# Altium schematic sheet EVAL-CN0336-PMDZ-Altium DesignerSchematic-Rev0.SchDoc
size A
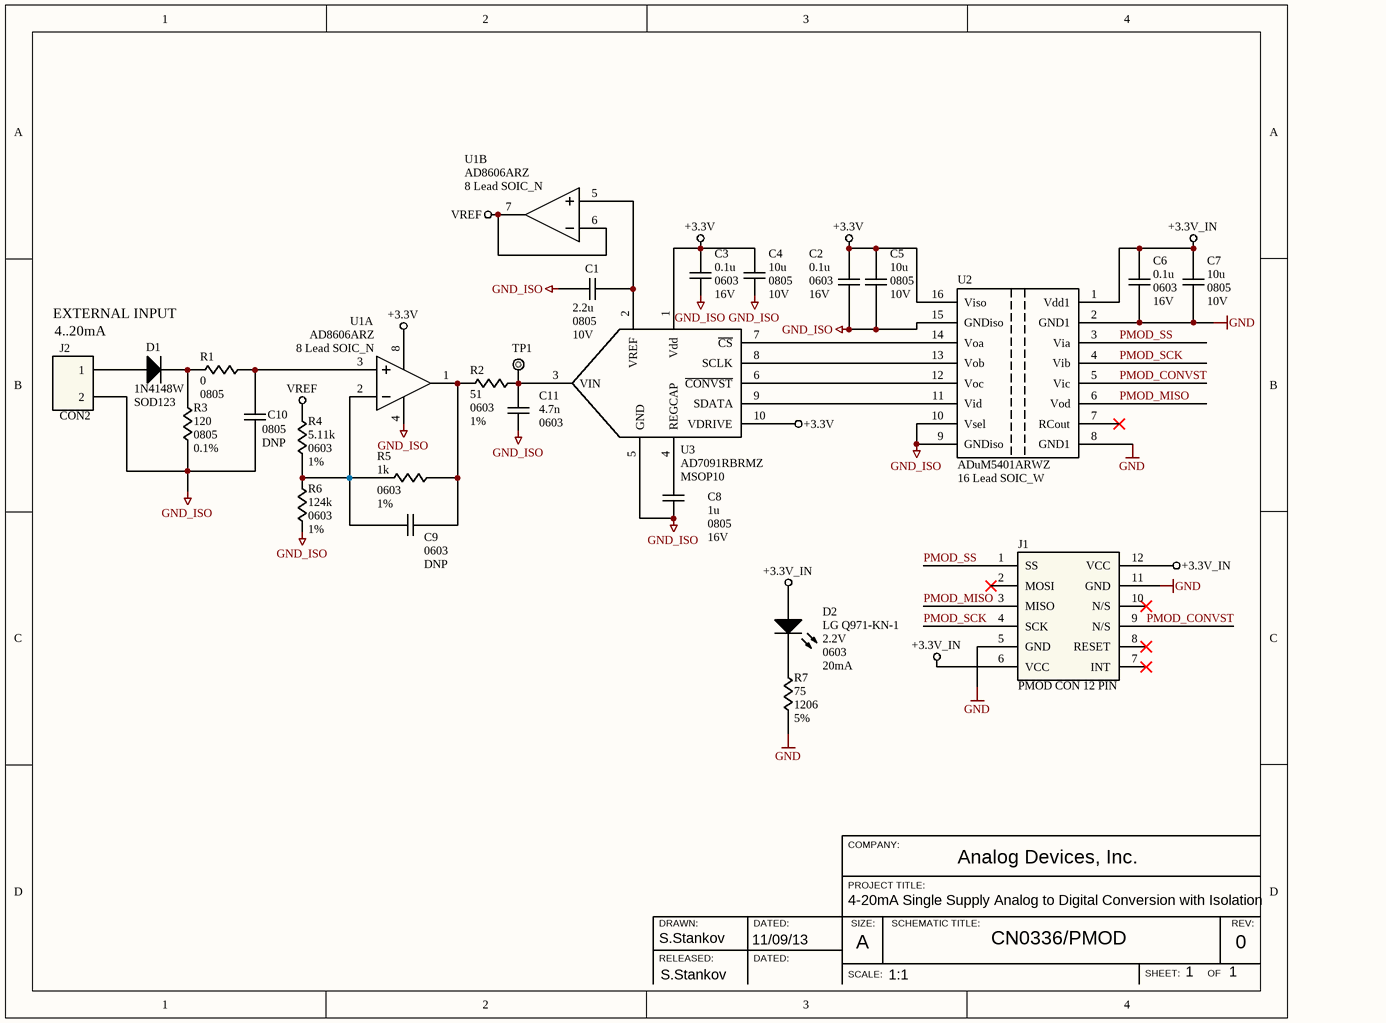
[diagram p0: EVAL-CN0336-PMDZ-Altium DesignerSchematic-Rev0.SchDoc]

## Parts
C1  value 2.2u  Footprint: 0805  Voltage: 10V  [0805 AD]
C2  value 0.1u  Footprint: 0603  Voltage: 16V  [0603 AD]
C3  value 0.1u  Footprint: 0603  Voltage: 16V  [0603 AD]
C4  value 10u  Footprint: 0805  Voltage: 10V  [0805 AD]
C5  value 10u  Footprint: 0805  Voltage: 10V  [0805 AD]  (hidden comment: Cap)
C6  value 0.1u  Footprint: 0603  Voltage: 16V  [0603 AD]
C7  value 10u  Footprint: 0805  Voltage: 10V  [0805 AD]  (hidden comment: Cap)
C8  value 1u  Footprint: 0805  Voltage: 16V  [0805 AD]
C9  Footprint: 0603  Part Number: DNP  [0603 AD]
C10  Footprint: 0805  Part Number: DNP  [0805 AD]
C11  value 4.7n  Footprint: 0603  [0603 AD]
D1  value 1N4148W  [SOD123]
D2  value LG Q971-KN-1  Drop Voltage: 2.2V  Footprint: 0603  Current: 20mA  [0603 Diode]  (hidden comment: LED3)
J1  PMOD CON 12 Pin  [PMOD 12 Pin]
J2  CON 2  [Phoenix Klema pitch 2_54]  (value not drawn)
R1  value 0  Footrprint: 0805  [0805 AD]  (hidden comment: RESISTOR)
R2  value 51  Footrprint: 0603  Tolerance: 1%  [0603 AD]  (hidden comment: RESISTOR)
R3  value 120  Footrprint: 0805  Tolerance: 0.1%  [0805 AD]  (hidden comment: RESISTOR)
R4  value 5.11k  Footrprint: 0603  Tolerance: 1%  [0603 AD]  (hidden comment: RESISTOR)
R5  value 1k  Footrprint: 0603  Tolerance: 1%  [0603 AD]  (hidden comment: RESISTOR)
R6  value 124k  Footrprint: 0603  Tolerance: 1%  [0603 AD]  (hidden comment: RESISTOR)
R7  value 75  Footrprint: 1206  Tolerance: 5%  [1206 AD]  (hidden comment: RESISTOR)
TP1  TestPoint  (value not drawn)
U1  value AD8606ARZ  Footprint: 8 Lead SOIC_N  [SOICN_8]  (hidden comment: AD8606)  (parts A,B of 2)
U2  value ADuM5401ARWZ  Footprint: 16 Lead SOIC_W  [SOICW_16]  (hidden comment: ADuM5401)
U3  value AD7091RBRMZ  [MSOP10]  (hidden comment: AD7091R)

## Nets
+3.3V: C2.2 C3.1 C4.1 C5.2 U1.8(V+) U2.16(Viso) U3.1(Vdd) U3.10(VDRIVE)
+3.3V_IN: C6.2 C7.2 D2.A J1.6(VCC) J1.12(VCC) U2.1(Vdd1)
GND: C6.1 C7.1 J1.5(GND) J1.11(GND) R7.1 U2.2(GND1) U2.8(GND1)
GND_ISO: C1.2 C2.1 C3.2 C4.2 C5.1 C8.2 C10.1 C11.1 J2.2 R3.1 R6.1 U1.4(V-) U2.9(GNDiso) U2.10(Vsel) U2.15(GNDiso) U3.5(GND)
VREF: R4.2 U1.6(-INB) U1.7(OUTB)
PMOD_CONVST: J1.9(N/S) U2.5(Vic)
PMOD_MISO: J1.3(MISO) U2.6(Vod)
PMOD_SCK: J1.4(SCK) U2.4(Vib)
PMOD_SS: J1.1(SS) U2.3(Via)
NetC1_1: C1.1 U1.5(+INB) U3.2(VREF)
NetC8_1: C8.1 U3.4(REGCAP)
NetC9_1: C9.1 R2.2 R5.1 U1.1(OUTA)
NetC9_2: C9.2 R4.1 R5.2 R6.2 U1.2(-INA)
NetC10_2: C10.2 R1.2 U1.3(+INA)
NetC11_2: C11.2 R2.1 TP1.Cathode U3.3(VIN)
NetD1_A: D1.A J2.1
NetD1_K: D1.K R1.1 R3.2
NetD2_K: D2.K R7.2
NetU2_11: U2.11(Vid) U3.9(SDATA)
NetU2_12: U2.12(Voc) U3.6(~{CONVST})
NetU2_13: U2.13(Vob) U3.8(SCLK)
NetU2_14: U2.14(Voa) U3.7(~{CS})

Not connected (* = marked no-connect by the designer): J1 2(MOSI)* 7(INT)* 8(RESET)* 10(N/S)*; U2 7(RCout)*

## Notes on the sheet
- EXTERNAL INPUT
- (near J2) 4..20mA
- COMPANY:
- PROJECT TITLE:
- 4-20mA Single Supply Analog to Digital Conversion with Isolation
- Analog Devices, Inc.
- DRAWN:
- RELEASED:
- S.Stankov
- 11/09/13
- DATED:
- SCALE:
- SIZE:
- A
- SCHEMATIC TITLE:
- CN0336/PMOD
- SHEET:           OF
- 1
- REV:
- 0
- 1:1

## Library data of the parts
C1 = Cap: Capacitor; Part Number: 7000305
C2 C3 C6 = Cap: Capacitor; Part Number: 7000814
C4 C5 C7 = Cap: Capacitor; Part Number: 7000461
C8 = Cap: Capacitor; Part Number: 7000143
C9 = Cap: Capacitor; Value: 0.1u; Voltage: 16V
C10 = Cap: Capacitor; Value: 1u; Voltage: 16V
C11 = Cap: Capacitor; Part Number: 7000387; Voltage: 16V
D1 = Diode: Part Number: 7001519
D2 = LED3: LED; Part Number: LG Q971-KN-1-0-20-R18
J1 = PMOD CON 12 Pin: PMOD CONNECTOR 12 PIN
J2 = CON 2: Input Connector
R1 = RESISTOR: Part Number: 7000228
R2 = RESISTOR: Part Number: 7001199
R4 = RESISTOR: Part Number: 7000731
R5 = RESISTOR: Part Number: 7001194
R6 = RESISTOR: Part Number: 7000931
R7 = RESISTOR: Part Number: 7001191
U1 = AD8606: Dual Operational Amplifier; Part Number: 30-025209-01
U2 = ADuM5401: Quad Digital Isolator with integrated DC/DC converter; Part Number: 30-025173-01
U3 = AD7091R: ADC; Part Number: 30-026273-01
